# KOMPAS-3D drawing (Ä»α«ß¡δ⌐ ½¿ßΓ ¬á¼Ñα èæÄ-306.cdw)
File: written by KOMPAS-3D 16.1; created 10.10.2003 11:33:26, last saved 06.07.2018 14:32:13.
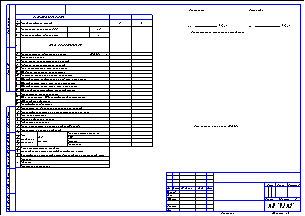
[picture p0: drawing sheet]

Sheet 1: A3, landscape

Title block, sheet 1: sheets: 1; organisation: АО "ЧЭАЗ"; sheet format: A3; stored path: D:\Заказы\Уфа\Схема монтажа №1.cdw

Views: Вид, Вид 1, Вид 2, Вид 3, Вид 4, Вид 6, Вид 7, Вид 10, Вид 11
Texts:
  Локальный фрагмент 1
  Normal
  Body Text
  heading 1
  heading 2
  heading 3
  heading 4
  heading 5
  heading 6
  heading 7
  heading 8
  heading 9
  Body Text 2
  header
  caption
  footer
  toc 1
  toc 2
  toc 3
  toc 4
  toc 5
  toc 6
  toc 7
  toc 8
  toc 9
  Body Text Indent 2
  annotation text
  Plain Text
  Courier New
  Body Text Indent 3
  Title
  Document Map
  Tahoma
  Body Text 3
  Block Text
  ArialMT
  font5
  font6
  font7
  xl24
  xl25
  xl26
  xl27
  xl28
  xl29
  xl30
  xl31
  xl32
  xl33
  xl34
  xl35
  xl36
  xl37
  xl38
  xl39
  xl40
  xl41
  xl42
  xl43
  xl44
  xl45
  xl46
  xl47
  xl48
  xl49
  xl50
  xl51
  xl52
  xl53
  xl54
  xl55
  xl56
  xl57
  xl58
  xl59
  xl60
  xl61
  xl62
  xl63
  xl64
  xl65
  xl66
  xl67
  xl68
  xl69
  xl70
  xl71
  xl72
  xl73
  xl74
  xl75
  xl76
  xl77
  xl78
  xl79
  xl80
  xl81
  xl82
  xl83
  xl84
  xl85
  xl86
  xl87
  xl88
  xl89
  xl90
  xl91
  xl92
  xl93
  xl94
  xl95
  xl96
  xl97
  xl98
  xl99
  xl100
  xl101
  xl102
  xl103
  xl104
  xl105
  xl106
  xl107
  xl108
  xl109
  xl110
  xl111
  xl112
  xl113
  xl114
  xl115
  xl116
  xl117
  xl118
  xl119
  xl120
  xl121
  xl122
  xl123
  xl124
  xl125
  xl126
  xl127
  xl128
  xl129
  xl130
  xl131
  xl132
  xl133
  xl134
  Iniiaiie oaeno
  xl22
  xl23
  Лит-Масса-Масштаб
  Материал-Предприятие
  textp
  Title Specification
  Body Specification ( left align )
  Body Specificaton ( centered )
  russ
  Definition Term
  Definition List
  Address
  Blockquote
  Preformatted
  z-Bottom of Form
  z-Top of Form
  ЗАПРАШИВАЕМЫЕ ДАННЫЕ
  № поз
  Порядковый номер шкафа
  Номинальное напряжение КСО
  Номинальный ток сборных шин
  СХЕМА ГЛАВНЫХ ЦЕПЕЙ
  Номенклатурное обозначение камеры                     КСО-306____-
  Назначение камеры
  Номер схемы вспомогательных цепей
  Род тока вспомогательных цепей
  Комм. аппарат., тип, ток, напряжение
  Тип блока управления выключателя
  Ремонтное освещение камеры / розетка
  Трансформатор собственных нужд, тип, напряжение
  Трансформатор тока, тип. класс точности
  Трансформатор напряжения, тип, напряжение
  Тип предохранителей, ток плавкой вставки
  Ограничитель перенапряжения
  Тип и количество ТТ нулевой последовательности
  Шинный разъединитель
  Линейный разъединитель
  Количество эл. бл./замков заземляющих ножей
  Конечный выключатель на главные/заземляющие ножи
  Реле промежуточное
  Наличие обогрева в камере
  Индикатор напряжения
  Марка, количество и сечение кабелей до ввода
  Количество и сечение кабелей
  Реле,
  требующие
  уточнения
  защиты
  Защита от замыкания на
  МТЗ
  Отсечка
  Перегрузка
  В комплект поставки входят:
  шинный мост  - шт., правый боковой экран - шт.,
  боковой экран с.ш. левый  - шт., боковой экран с.ш. правый - шт.
  Заказчик:
  Объект:
  Проектная организация:
  Дополнительные технические требования
  Согласовано
  Утверждаю
  План расположения камер КСО-306
  GEN7_RGB_0_0_0_SC_1_THICK_0.18
  K5LT_THIN_RGB_0_0_0_THICK_0.18
  K5LT32769_RGB_0_0_0_THICK_0.18
Dimensions and other numbers on the sheet: 1; 2; 3; 4; 5; 6; 7; 8; 9; 10; 11; 12; 13; 14; 15; 16; 17; 18; 19; 20; 21; 22; 23; 24; 25; 26; 27; 28; 29; 30; 31; 32; 33; 34; 20__ г.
